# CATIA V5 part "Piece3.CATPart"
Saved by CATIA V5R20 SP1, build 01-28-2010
Part number: Piece3
Bounding box of the stored display mesh (mm): x 18.735 to 60.295, y 116.378 to 193.749, z -267.497 to 14.986
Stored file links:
  C:\Users\RENARD Simon\Documents\Cours IFMA\2ème année\IAO\Piece3.CATPart
  C:\Users\RENARD Simon\Documents\Cours IFMA\2ème année\IAO\Trainattero.CATProduct
  C:\Users\RENARD Simon\Documents\Cours IFMA\2ème année\IAO\Sqpiece3.CATPart
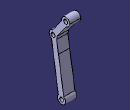
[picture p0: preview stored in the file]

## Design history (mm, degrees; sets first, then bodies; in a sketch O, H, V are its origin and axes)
Set1
  Plane1: linked copy from another document
  Line1 to Line3: linked copy from another document
Body1 (main body)
  Sketch1 on Plane1, origin (36.3239, -0.7439, 0), H (0.0205, 0.9998, 0), V (0, 0, 1)
    arc A1 centre (163.5883, -252.4969) radius 15 from (151.9884, -242.9868) to (171.7507, -239.9121) ccw
    point P1 (163.5883, -252.4969)
    arc A2 centre (132.5551, -65.0484) radius 15 from (130.9323, -50.1364) to (126.4349, -78.743) ccw
    point P2 (132.5551, -65.0484)
    arc A3 centre (179.1245, 0) radius 15 from (194.1245, 0) to (164.4852, -3.2696) ccw
    point P3 (179.1245, 0)
    reference projected point E1 (163.5883, -252.4969) from Line1
    reference projected point E2 (132.5551, -65.0484) from Line2
    reference projected point E3 (179.1245, 0) from Line3
    line L1 (126.4349, -78.743) -> (151.9884, -242.9868)
    point P6 (145.6758, -72.3179)
    line L2 (145.6758, -72.3179) -> (152.4644, -115.951)
    point P8 (180.7473, -14.912)
    line L3 (180.7473, -14.912) -> (147.1944, -61.7788)
    line L4 (164.4852, -3.2696) -> (130.9323, -50.1364)
    reference projected point E4 (163.5883, -252.4969) from Line1
    reference projected point E5 (179.1245, 0) from Line3
    reference projected point E6 (132.5551, -65.0484) from Line2
    arc A4 centre (179.1245, 0) radius 15 from (180.7473, -14.912) to (194.1245, 0) ccw
    point P12 (194.1245, 0)
    point P13 (194.1245, 0)
    line L5 (152.4644, -115.951) -> (171.7507, -239.9121)
    arc A5 centre (132.5551, -65.0484) radius 15 from (145.6758, -72.3179) to (147.1944, -61.7788) ccw
    radius A1 = 15
    radius A2 = 15
    radius A3 = 15
    distance L2 L1 = 20
    distance L2 E4 = 10
    distance L3 E5 = 10
    distance L4 L3 = 20
    distance E6 L3 = 10
    coincidence: P3 H, P1 E1, P2 E2, P3 E3, P6 A2, P8 A3, A3 A4, L2 L5, A2 A5, P12 P13
    parallelism: L2 L1
  Pad1: profile Sketch1, direction (0.9998, -0.0205, 0), length 20, mirrored extent
  Sketch2 on start face of Pad1, origin (16.3281, -0.3344, 0), H (-0.0205, -0.9998, 0), V (0, 0, 1)
    circle A1 centre (-179.1245, 0) radius 7.5
    point P1 (-179.1245, 0)
    point P2 (-186.6245, 0)
    circle A2 centre (-132.5551, -65.0484) radius 7.5
    point P3 (-132.5551, -65.0484)
    circle A3 centre (-163.5883, -252.4969) radius 7.5
    point P4 (-163.5883, -252.4969)
    reference projected point E1 (-163.5883, -252.4969) from Line1
    reference projected point E2 (-132.5551, -65.0484) from Line2
    reference projected point E3 (-179.1245, 0) from Line3
    radius A3 = 7.5
    radius A1 = 7.5
    radius A2 = 7.5
    coincidence: A1 P2, P2 H, P4 E1, P3 E2, P1 E3
  Pocket1: profile Sketch2, direction (0.9998, -0.0205, 0), length 40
